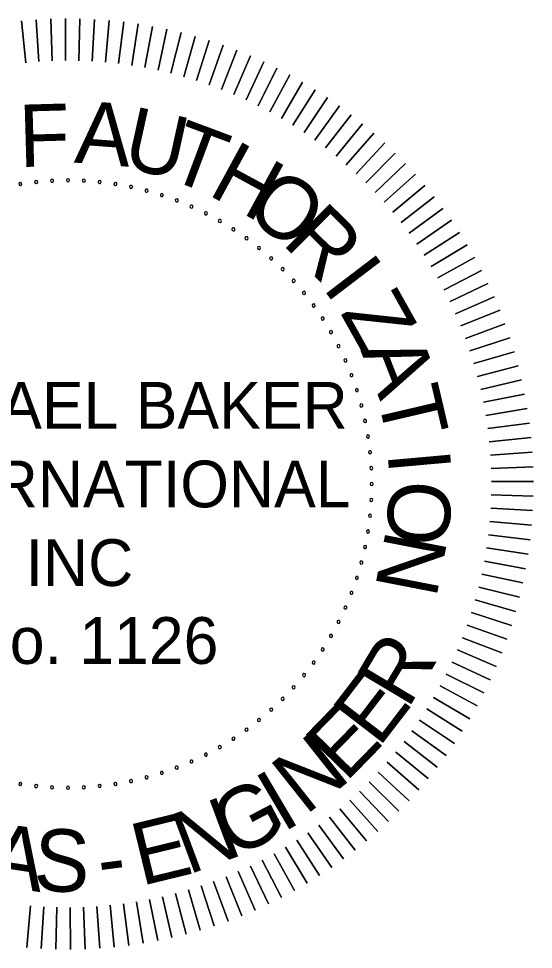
# Model space of a CAD drawing. Extents: x 166 to 3406, y 71 to 2074.
# Drawn here: x 2890.7 to 3028.3, y 403 to 651.9 of the extents above; entities that cross this region are included whole.
import ezdxf

# ---------------------------------------------------------------- set-up
doc = ezdxf.new("R2010")
doc.units = 0
doc.layers.add('G-ANNO-TEXT', color=7, linetype='Continuous')

msp = doc.modelspace()

# ---------------------------------------------------------------- linework, layer by layer
at = {"layer": 'G-ANNO-TEXT'}
for points in [[(2892.59, 640.07), (2891.47, 651.23)], [(2891.47, 651.23), (2892.59, 640.07)], [(2896.13, 640.37), (2895.36, 651.56)], [(2895.36, 651.56), (2896.13, 640.37)], [(2899.68, 640.55), (2899.27, 651.77)], [(2899.27, 651.77), (2899.68, 640.55)], [(2903.24, 640.63), (2903.18, 651.85)], [(2903.18, 651.85), (2903.24, 640.63)], [(2906.8, 640.59), (2907.09, 651.81)], [(2907.09, 651.81), (2906.8, 640.59)], [(2910.35, 640.44), (2910.99, 651.65)], [(2910.99, 651.65), (2910.35, 640.44)], [(2913.9, 640.19), (2914.89, 651.36)], [(2914.89, 651.36), (2913.9, 640.19)], [(2917.43, 639.81), (2918.78, 650.96)], [(2918.78, 650.96), (2917.43, 639.81)], [(2920.96, 639.33), (2922.65, 650.43)], [(2922.65, 650.43), (2920.96, 639.33)], [(2924.46, 638.74), (2926.51, 649.78)], [(2926.51, 649.78), (2924.46, 638.74)], [(2927.95, 638.04), (2930.34, 649.01)], [(2930.34, 649.01), (2927.95, 638.04)], [(2931.41, 637.23), (2934.14, 648.11)], [(2934.14, 648.11), (2931.41, 637.23)], [(2934.85, 636.31), (2937.92, 647.1)], [(2937.92, 647.1), (2934.85, 636.31)], [(2938.26, 635.28), (2941.66, 645.97)], [(2941.66, 645.97), (2938.26, 635.28)], [(2941.63, 634.15), (2945.37, 644.73)], [(2945.37, 644.73), (2941.63, 634.15)], [(2944.96, 632.91), (2949.03, 643.37)], [(2949.03, 643.37), (2944.96, 632.91)], [(2948.25, 631.57), (2952.65, 641.89)], [(2952.65, 641.89), (2948.25, 631.57)], [(2951.5, 630.12), (2956.23, 640.3)], [(2956.23, 640.3), (2951.5, 630.12)], [(2954.71, 628.57), (2959.75, 638.6)], [(2959.75, 638.6), (2954.71, 628.57)], [(2957.86, 626.93), (2963.21, 636.79)], [(2963.21, 636.79), (2957.86, 626.93)], [(2960.96, 625.18), (2966.62, 634.87)], [(2966.62, 634.87), (2960.96, 625.18)], [(2964, 623.34), (2969.96, 632.85)], [(2969.96, 632.85), (2964, 623.34)], [(2966.99, 621.41), (2973.24, 630.72)], [(2973.24, 630.72), (2966.99, 621.41)], [(2969.91, 619.38), (2976.45, 628.49)], [(2976.45, 628.49), (2969.91, 619.38)], [(2972.76, 617.26), (2979.59, 626.16)], [(2979.59, 626.16), (2972.76, 617.26)], [(2975.55, 615.05), (2982.66, 623.74)], [(2982.66, 623.74), (2975.55, 615.05)], [(2978.27, 612.75), (2985.64, 621.21)], [(2985.64, 621.21), (2978.27, 612.75)], [(2988.55, 618.6), (2980.91, 610.37)], [(2980.91, 610.37), (2988.55, 618.6)], [(2991.37, 615.89), (2983.48, 607.91)], [(2983.48, 607.91), (2991.37, 615.89)], [(2994.11, 613.1), (2985.97, 605.37)], [(2985.97, 605.37), (2994.11, 613.1)], [(2996.75, 610.22), (2988.38, 602.76)], [(2988.38, 602.76), (2996.75, 610.22)], [(2999.31, 607.27), (2990.7, 600.06)], [(2990.7, 600.06), (2999.31, 607.27)], [(3001.77, 604.23), (2992.94, 597.3)], [(2992.94, 597.3), (3001.77, 604.23)], [(3004.14, 601.12), (2995.09, 594.47)], [(2995.09, 594.47), (3004.14, 601.12)], [(3006.4, 597.93), (2997.15, 591.57)], [(2997.15, 591.57), (3006.4, 597.93)], [(3008.57, 594.67), (2999.12, 588.61)], [(2999.12, 588.61), (3008.57, 594.67)], [(3010.63, 591.35), (3001, 585.59)], [(3001, 585.59), (3010.63, 591.35)], [(3012.58, 587.97), (3002.78, 582.51)], [(3002.78, 582.51), (3012.58, 587.97)], [(3014.43, 584.52), (3004.46, 579.37)], [(3004.46, 579.37), (3014.43, 584.52)], [(3016.17, 581.02), (3006.04, 576.19)], [(3006.04, 576.19), (3016.17, 581.02)], [(3017.8, 577.47), (3007.52, 572.95)], [(3007.52, 572.95), (3017.8, 577.47)], [(3019.31, 573.87), (3008.9, 569.68)], [(3008.9, 569.68), (3019.31, 573.87)], [(3020.72, 570.22), (3010.18, 566.36)], [(3010.18, 566.36), (3020.72, 570.22)], [(3022, 566.52), (3011.35, 563)], [(3011.35, 563), (3022, 566.52)], [(3023.17, 562.79), (3012.42, 559.6)], [(3012.42, 559.6), (3023.17, 562.79)], [(3024.23, 559.03), (3013.37, 556.18)], [(3013.37, 556.18), (3024.23, 559.03)], [(3025.16, 555.23), (3014.22, 552.72)], [(3014.22, 552.72), (3025.16, 555.23)], [(3025.97, 551.41), (3014.96, 549.25)], [(3014.96, 549.25), (3025.97, 551.41)], [(3026.67, 547.56), (3015.59, 545.75)], [(3015.59, 545.75), (3026.67, 547.56)], [(3027.24, 543.7), (3016.11, 542.23)], [(3016.11, 542.23), (3027.24, 543.7)], [(3027.69, 539.81), (3016.52, 538.69)], [(3016.52, 538.69), (3027.69, 539.81)], [(3028.02, 535.92), (3016.82, 535.15)], [(3016.82, 535.15), (3028.02, 535.92)], [(3028.23, 532.01), (3017.01, 531.6)], [(3017.01, 531.6), (3028.23, 532.01)], [(3028.31, 528.1), (3017.09, 528.04)], [(3017.09, 528.04), (3028.31, 528.1)], [(3028.27, 524.2), (3017.05, 524.49)], [(3017.05, 524.49), (3028.27, 524.2)], [(3028.11, 520.29), (3016.9, 520.93)], [(3016.9, 520.93), (3028.11, 520.29)], [(3027.82, 516.39), (3016.64, 517.38)], [(3016.64, 517.38), (3027.82, 516.39)], [(3027.41, 512.5), (3016.27, 513.85)], [(3016.27, 513.85), (3027.41, 512.5)], [(3026.89, 508.63), (3015.79, 510.32)], [(3015.79, 510.32), (3026.89, 508.63)], [(3026.23, 504.77), (3015.2, 506.82)], [(3015.2, 506.82), (3026.23, 504.77)], [(3025.46, 500.94), (3014.5, 503.33)], [(3014.5, 503.33), (3025.46, 500.94)], [(3024.57, 497.14), (3013.69, 499.87)], [(3013.69, 499.87), (3024.57, 497.14)], [(3023.56, 493.36), (3012.77, 496.43)], [(3012.77, 496.43), (3023.56, 493.36)], [(3022.43, 489.62), (3011.74, 493.03)], [(3011.74, 493.03), (3022.43, 489.62)], [(3021.19, 485.91), (3010.61, 489.65)], [(3010.61, 489.65), (3021.19, 485.91)], [(3019.83, 482.25), (3009.37, 486.32)], [(3009.37, 486.32), (3019.83, 482.25)], [(3018.35, 478.63), (3008.03, 483.03)], [(3008.03, 483.03), (3018.35, 478.63)], [(3016.76, 475.06), (3006.58, 479.78)], [(3006.58, 479.78), (3016.76, 475.06)], [(3015.06, 471.54), (3005.03, 476.57)], [(3005.03, 476.57), (3015.06, 471.54)], [(3013.25, 468.07), (3003.39, 473.42)], [(3003.39, 473.42), (3013.25, 468.07)], [(3011.33, 464.66), (3001.64, 470.32)], [(3001.64, 470.32), (3011.33, 464.66)], [(3009.31, 461.32), (2999.8, 467.28)], [(2999.8, 467.28), (3009.31, 461.32)], [(3007.18, 458.04), (2997.86, 464.3)], [(2997.86, 464.3), (3007.18, 458.04)], [(3004.95, 454.83), (2995.83, 461.37)], [(2995.83, 461.37), (3004.95, 454.83)], [(3002.62, 451.69), (2993.72, 458.52)], [(2993.72, 458.52), (3002.62, 451.69)], [(3000.19, 448.63), (2991.51, 455.73)], [(2991.51, 455.73), (3000.19, 448.63)], [(2997.67, 445.64), (2989.21, 453.01)], [(2989.21, 453.01), (2997.67, 445.64)], [(2995.06, 442.73), (2986.83, 450.37)], [(2986.83, 450.37), (2995.06, 442.73)], [(2992.35, 439.91), (2984.37, 447.8)], [(2984.37, 447.8), (2992.35, 439.91)], [(2989.56, 437.17), (2981.83, 445.31)], [(2981.83, 445.31), (2989.56, 437.17)], [(2983.72, 431.97), (2976.52, 440.58)], [(2976.52, 440.58), (2983.72, 431.97)], [(2986.68, 434.53), (2979.21, 442.9)], [(2979.21, 442.9), (2986.68, 434.53)], [(2980.69, 429.51), (2973.76, 438.34)], [(2973.76, 438.34), (2980.69, 429.51)], [(2977.57, 427.15), (2970.93, 436.19)], [(2970.93, 436.19), (2977.57, 427.15)], [(2974.39, 424.88), (2968.03, 434.13)], [(2968.03, 434.13), (2974.39, 424.88)], [(2971.13, 422.72), (2965.07, 432.16)], [(2965.07, 432.16), (2971.13, 422.72)], [(2964.43, 418.7), (2958.97, 428.5)], [(2958.97, 428.5), (2964.43, 418.7)], [(2967.81, 420.65), (2962.04, 430.28)], [(2962.04, 430.28), (2967.81, 420.65)], [(2960.98, 416.85), (2955.83, 426.82)], [(2955.83, 426.82), (2960.98, 416.85)], [(2953.93, 413.48), (2949.41, 423.76)], [(2949.41, 423.76), (2953.93, 413.48)], [(2957.48, 415.11), (2952.65, 425.24)], [(2952.65, 425.24), (2957.48, 415.11)], [(2946.67, 410.56), (2942.81, 421.1)], [(2942.81, 421.1), (2946.67, 410.56)], [(2950.32, 411.97), (2946.13, 422.38)], [(2946.13, 422.38), (2950.32, 411.97)], [(2939.25, 408.11), (2936.06, 418.87)], [(2936.06, 418.87), (2939.25, 408.11)], [(2942.98, 409.28), (2939.46, 419.93)], [(2939.46, 419.93), (2942.98, 409.28)], [(2924.02, 404.61), (2922.2, 415.69)], [(2922.2, 415.69), (2924.02, 404.61)], [(2927.87, 405.31), (2925.7, 416.32)], [(2925.7, 416.32), (2927.87, 405.31)], [(2931.69, 406.12), (2929.18, 417.06)], [(2929.18, 417.06), (2931.69, 406.12)], [(2935.49, 407.05), (2932.64, 417.91)], [(2932.64, 417.91), (2935.49, 407.05)], [(2892.85, 403.46), (2893.84, 414.64)], [(2893.84, 414.64), (2892.85, 403.46)], [(2896.75, 403.17), (2897.39, 414.38)], [(2897.39, 414.38), (2896.75, 403.17)], [(2900.65, 403.01), (2900.94, 414.23)], [(2900.94, 414.23), (2900.65, 403.01)], [(2904.56, 402.97), (2904.5, 414.19)], [(2904.5, 414.19), (2904.56, 402.97)], [(2908.47, 403.06), (2908.06, 414.27)], [(2908.06, 414.27), (2908.47, 403.06)], [(2912.38, 403.26), (2911.61, 414.46)], [(2911.61, 414.46), (2912.38, 403.26)], [(2916.27, 403.59), (2915.15, 414.76)], [(2915.15, 414.76), (2916.27, 403.59)], [(2920.15, 404.04), (2918.69, 415.17)], [(2918.69, 415.17), (2920.15, 404.04)]]:
    msp.add_lwpolyline(points, dxfattribs=at)
for centre, start, end in [((2891.16, 607.63), 9, 189), ((2891.16, 607.63), 189, 9), ((2895.38, 608.18), 6, 186), ((2895.38, 608.18), 186, 6), ((2899.62, 608.51), 3, 183), ((2899.62, 608.51), 183, 3), ((2903.87, 608.63), 0, 180), ((2903.87, 608.63), 180, 0), ((2908.12, 608.51), 357, 177), ((2908.12, 608.51), 177, 357), ((2912.36, 608.18), 354, 174), ((2912.36, 608.18), 174, 354), ((2916.57, 607.63), 351, 171), ((2916.57, 607.63), 171, 351), ((2920.76, 606.85), 348, 168), ((2920.76, 606.85), 168, 348), ((2924.89, 605.86), 165, 345), ((2924.89, 605.86), 345, 165), ((2928.97, 604.65), 162, 342), ((2928.97, 604.65), 342, 162), ((2932.97, 603.23), 159, 339), ((2932.97, 603.23), 339, 159), ((2936.9, 601.6), 156, 336), ((2936.9, 601.6), 336, 156), ((2940.74, 599.77), 153, 333), ((2940.74, 599.77), 333, 153), ((2944.48, 597.75), 150, 330), ((2944.48, 597.75), 330, 150), ((2948.1, 595.52), 147, 327), ((2948.1, 595.52), 327, 147), ((2951.61, 593.12), 144, 324), ((2951.61, 593.12), 324, 144), ((2954.98, 590.53), 141, 321), ((2954.98, 590.53), 321, 141), ((2958.21, 587.77), 138, 318), ((2958.21, 587.77), 318, 138), ((2961.3, 584.84), 135, 315), ((2961.3, 584.84), 315, 135), ((2964.22, 581.75), 132, 312), ((2964.22, 581.75), 312, 132), ((2966.99, 578.52), 129, 309), ((2966.99, 578.52), 309, 129), ((2969.57, 575.15), 126, 306), ((2969.57, 575.15), 306, 126), ((2971.98, 571.64), 123, 303), ((2971.98, 571.64), 303, 123), ((2974.2, 568.02), 120, 300), ((2974.2, 568.02), 300, 120), ((2976.23, 564.28), 117, 297), ((2976.23, 564.28), 297, 117), ((2978.06, 560.44), 114, 294), ((2978.06, 560.44), 294, 114), ((2979.69, 556.52), 111, 291), ((2979.69, 556.52), 291, 111), ((2981.11, 552.51), 108, 288), ((2981.11, 552.51), 288, 108), ((2982.32, 548.43), 105, 285), ((2982.32, 548.43), 285, 105), ((2983.31, 544.3), 102, 282), ((2983.31, 544.3), 282, 102), ((2984.08, 540.12), 99, 279), ((2984.08, 540.12), 279, 99), ((2984.64, 535.9), 96, 276), ((2984.64, 535.9), 276, 96), ((2984.97, 531.66), 93, 273), ((2984.97, 531.66), 273, 93), ((2985.08, 527.41), 90, 270), ((2985.08, 527.41), 270, 90), ((2984.97, 523.16), 87, 267), ((2984.97, 523.16), 267, 87), ((2984.64, 518.92), 84, 264), ((2984.64, 518.92), 264, 84), ((2984.08, 514.71), 81, 261), ((2984.08, 514.71), 261, 81), ((2983.31, 510.53), 78, 258), ((2983.31, 510.53), 258, 78), ((2982.32, 506.39), 75, 255), ((2982.32, 506.39), 255, 75), ((2981.11, 502.31), 72, 252), ((2981.11, 502.31), 252, 72), ((2979.69, 498.31), 69, 249), ((2979.69, 498.31), 249, 69), ((2978.06, 494.38), 66, 246), ((2978.06, 494.38), 246, 66), ((2976.23, 490.54), 63, 243), ((2976.23, 490.54), 243, 63), ((2974.2, 486.8), 60, 240), ((2974.2, 486.8), 240, 60), ((2971.98, 483.18), 57, 237), ((2971.98, 483.18), 237, 57), ((2969.57, 479.67), 54, 234), ((2969.57, 479.67), 234, 54), ((2966.99, 476.3), 51, 231), ((2966.99, 476.3), 231, 51), ((2964.22, 473.07), 48, 228), ((2964.22, 473.07), 228, 48), ((2961.3, 469.98), 45, 225), ((2961.3, 469.98), 225, 45), ((2958.21, 467.06), 42, 222), ((2958.21, 467.06), 222, 42), ((2954.98, 464.3), 39, 219), ((2954.98, 464.3), 219, 39), ((2951.61, 461.71), 36, 216), ((2951.61, 461.71), 216, 36), ((2948.1, 459.3), 33, 213), ((2948.1, 459.3), 213, 33), ((2940.74, 455.05), 27, 207), ((2944.48, 457.08), 30, 210), ((2944.48, 457.08), 210, 30), ((2936.9, 453.22), 24, 204), ((2936.9, 453.22), 204, 24), ((2940.74, 455.05), 207, 27), ((2928.97, 450.17), 18, 198), ((2932.97, 451.59), 21, 201), ((2932.97, 451.59), 201, 21), ((2920.76, 447.97), 12, 192), ((2920.76, 447.97), 192, 12), ((2924.89, 448.96), 15, 195), ((2924.89, 448.96), 195, 15), ((2928.97, 450.17), 198, 18), ((2891.16, 447.2), 351, 171), ((2891.16, 447.2), 171, 351), ((2895.38, 446.64), 174, 354), ((2895.38, 446.64), 354, 174), ((2899.62, 446.31), 357, 177), ((2899.62, 446.31), 177, 357), ((2903.87, 446.2), 0, 180), ((2903.87, 446.2), 180, 0), ((2908.12, 446.31), 3, 183), ((2908.12, 446.31), 183, 3), ((2912.36, 446.64), 6, 186), ((2912.36, 446.64), 186, 6), ((2916.57, 447.2), 9, 189), ((2916.57, 447.2), 189, 9)]:
    msp.add_arc(centre, 0.417, start, end, dxfattribs=at)

# ---------------------------------------------------------------- texts
for s, rotation, p in [('F', 1.5867, (2890.94, 612.14)), ('A', 355.5955, (2905.39, 613.37)), ('U', 347.5481, (2918, 612.18)), ('T', 339.5007, (2929.64, 609.4)), ('H', 331.4533, (2940.94, 604.94)), ('O', 323.4059, (2950.51, 599.67)), ('R', 315.3585, (2960.83, 591.77)), ('I', 307.3112, (2971.67, 580.03)), ('Z', 299.2638, (2976.56, 573.24)), ('A', 291.2164, (2982.03, 563.21)), ('T', 283.169, (2986.39, 551.42)), ('I', 275.1216, (2989.28, 535.82)), ('O', 267.0743, (2989.86, 528.66)), ('N', 259.0269, (2988.99, 515.55)), ('R', 59.2262, (2994.74, 466.97)), ('E', 52.4765, (2987, 456.71)), ('E', 45.7268, (2978.12, 447.43)), ('N', 38.4196, (2967.34, 438.64)), ('I', 30.5495, (2961.29, 434.04)), ('G', 27.7404, (2948.11, 427.05)), ('N', 20.4332, (2935.98, 422.84)), ('E', 13.6835, (2923.41, 419.9)), ('A', 351.1991, (2881.82, 420.53)), ('S', 357.9489, (2894.53, 418.68)), ('-', 7.5077, (2912.72, 418.64))]:
    msp.add_text(s, height=16.67, rotation=rotation, dxfattribs=at).set_placement(p)
for s, height, p in [('MICHAEL BAKER', 12.5016, (2843.04, 542.19)), (' INTERNATIONAL', 12.5016, (2841.03, 521.17)), ('INC', 12.502, (2892.55, 500.14)), (' No. 1126', 12.502, (2871.6, 479.31))]:
    msp.add_text(s, height=height, dxfattribs=at).set_placement(p)

doc.saveas('drawing.dxf')
